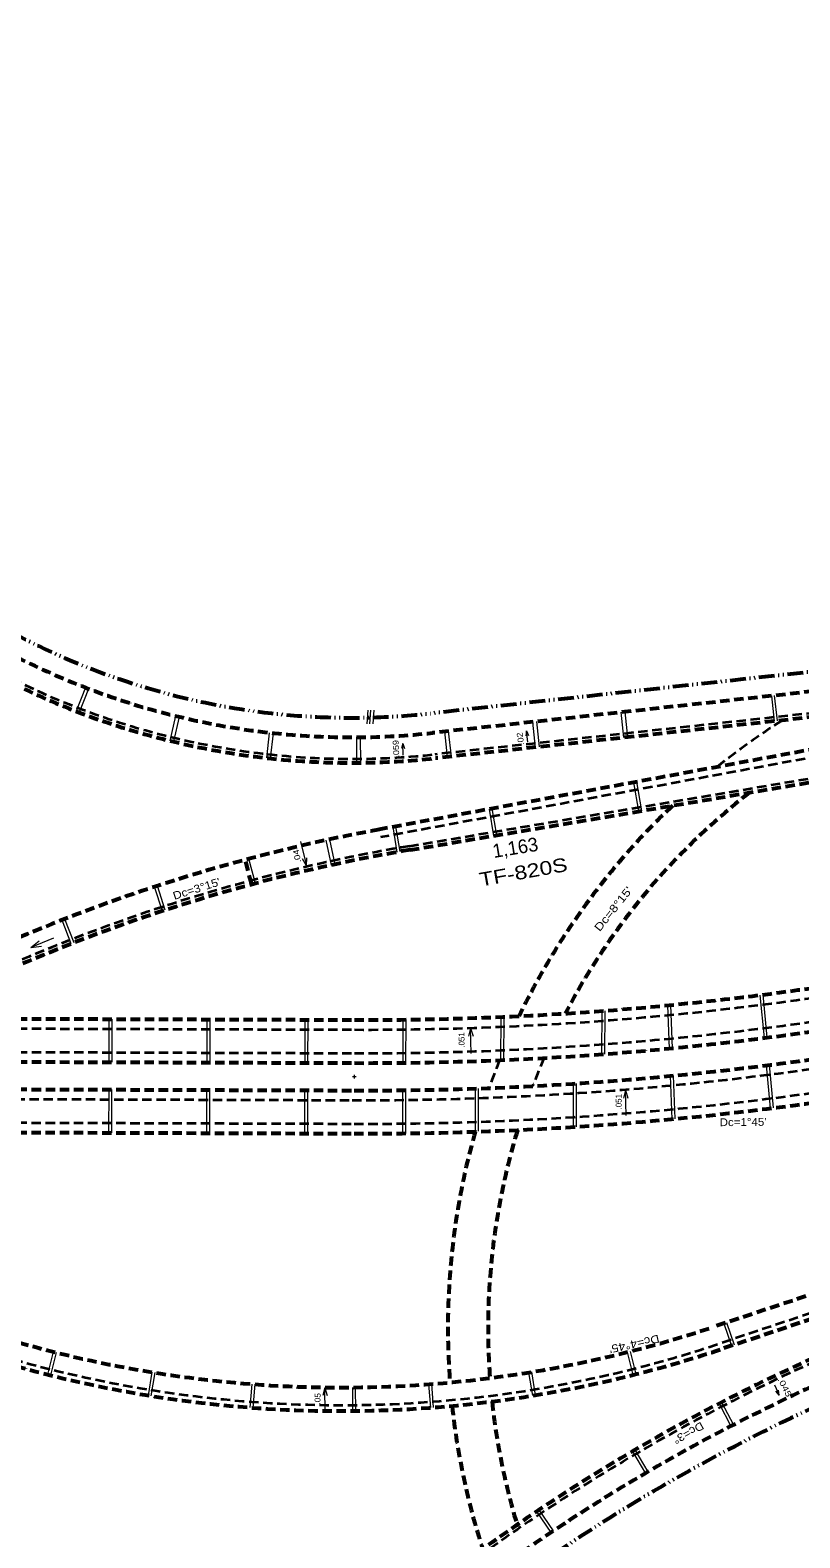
# Model space of a CAD drawing. Extents: x 2354993 to 2372084, y 6966390 to 6990057.
# Drawn here: x 2365274 to 2366060, y 6977519 to 6979057 of the extents above; entities that cross this region are included whole.
import ezdxf

# ---------------------------------------------------------------- set-up
doc = ezdxf.new("R2010")
doc.units = 0
doc.header["$LTSCALE"] = 3.2
doc.linetypes.add('DASH_DOUBLE_DOT', pattern=[9.2, 5, -1.2, 0.3, -1.2, 0.3, -1.2])
doc.linetypes.add('MEDIUM_DASHED', pattern=[4.5, 3, -1.5])
for name, color, linetype, lineweight in [('1', 7, 'Continuous', 13), ('12', 7, 'Continuous', 13), ('13', 7, 'Continuous', 13), ('14', 7, 'Continuous', 13), ('17', 7, 'Continuous', 13), ('19', 7, 'Continuous', 13), ('5', 7, 'Continuous', 35), ('60', 7, 'DASH_DOUBLE_DOT', 53), ('61', 7, 'Continuous', 13), ('7', 7, 'Continuous', 13), ('9', 7, 'Continuous', 13)]:
    doc.layers.add(name, color=color, linetype=linetype, lineweight=lineweight)

msp = doc.modelspace()

# ---------------------------------------------------------------- linework, layer by layer
at = {"layer": '1'}
for p, q in [((2365606.713, 6977989.566), (2365603.213, 6977989.566)), ((2365604.963, 6977991.316), (2365604.963, 6977987.816))]:
    msp.add_line(p, q, dxfattribs=at)
at = {"layer": '12'}
for p, q in [((2366036.779, 6978352.585), (2366033.959, 6978378.408)), ((2366033.797, 6978352.259), (2366030.977, 6978378.083)), ((2365895.358, 6978260.35), (2365890.38, 6978289.832)), ((2365898.314, 6978260.849), (2365893.33, 6978290.377)), ((2365747.452, 6978235.376), (2365742.862, 6978262.562)), ((2365750.406, 6978235.884), (2365745.811, 6978263.107)), ((2365648.848, 6978218.727), (2365644.516, 6978244.382)), ((2365651.801, 6978219.241), (2365647.465, 6978244.927)), ((2365504.061, 6978186.716), (2365497.424, 6978211.855)), ((2365409.176, 6978158.59), (2365401.125, 6978183.312)), ((2365412.028, 6978159.52), (2365403.977, 6978184.244)), ((2365316.038, 6978125.129), (2365306.599, 6978149.356)), ((2365318.832, 6978126.22), (2365309.393, 6978150.447)), ((2366019.03, 6978072.9), (2366023.149, 6978029.071)), ((2366022.008, 6978073.278), (2366026.127, 6978029.447)), ((2365857.509, 6978056.627), (2365857.359, 6978012.494)), ((2365860.51, 6978056.855), (2365860.36, 6978012.718)), ((2365924.585, 6978062.386), (2365926.463, 6978018.363)), ((2365927.576, 6978062.675), (2365929.455, 6978018.651)), ((2365354.478, 6978048.411), (2365354.33, 6978004.411)), ((2365357.477, 6978048.401), (2365357.329, 6978004.4)), ((2365454.478, 6978048.073), (2365454.33, 6978004.072)), ((2365457.477, 6978048.062), (2365457.329, 6978004.062)), ((2365554.478, 6978047.735), (2365554.329, 6978003.735)), ((2365557.477, 6978047.725), (2365557.329, 6978003.724)), ((2365654.478, 6978047.778), (2365654.33, 6978003.772)), ((2365657.478, 6978047.814), (2365657.328, 6978003.809)), ((2365754.488, 6978050.531), (2365754.339, 6978006.484)), ((2365757.488, 6978050.661), (2365757.339, 6978006.613)), ((2366029.859, 6977957.348), (2366025.825, 6978001.187)), ((2366032.838, 6977957.722), (2366028.804, 6978001.563)), ((2365828.595, 6977938.336), (2365828.744, 6977982.437)), ((2365831.596, 6977938.529), (2365831.745, 6977982.633)), ((2365929.451, 6977946.323), (2365927.714, 6977990.356)), ((2365932.442, 6977946.607), (2365930.706, 6977990.642)), ((2365354.235, 6977976.412), (2365354.087, 6977932.413)), ((2365357.234, 6977976.402), (2365357.086, 6977932.403)), ((2365454.235, 6977976.075), (2365454.086, 6977932.076)), ((2365457.234, 6977976.065), (2365457.086, 6977932.065)), ((2365554.235, 6977975.738), (2365554.086, 6977931.738)), ((2365557.234, 6977975.727), (2365557.086, 6977931.728)), ((2365654.235, 6977975.77), (2365654.087, 6977931.765)), ((2365657.235, 6977975.806), (2365657.086, 6977931.8)), ((2365728.579, 6977933.45), (2365728.727, 6977977.48)), ((2365731.581, 6977934.17), (2365731.728, 6977977.585)), ((2365982.067, 6977737.733), (2365989.826, 6977715.021)), ((2365984.913, 6977738.682), (2365992.673, 6977715.97)), ((2365297.64, 6977708.993), (2365291.783, 6977685.719)), ((2365300.55, 6977708.264), (2365294.693, 6977684.989)), ((2365883.51, 6977708.571), (2365889.375, 6977685.299)), ((2365886.419, 6977709.303), (2365892.284, 6977686.031)), ((2365398.24, 6977688.169), (2365394.396, 6977664.478)), ((2365401.201, 6977687.69), (2365397.357, 6977664)), ((2365782.833, 6977687.884), (2365786.685, 6977664.195)), ((2365785.794, 6977688.365), (2365789.646, 6977664.676)), ((2365500.263, 6977676.008), (2365498.461, 6977652.076)), ((2365503.255, 6977675.784), (2365501.453, 6977651.852)), ((2365602.982, 6977672.603), (2365603.236, 6977648.604)), ((2365605.981, 6977672.636), (2365606.236, 6977648.637)), ((2365680.749, 6977675.871), (2365682.559, 6977651.939)), ((2365683.74, 6977676.098), (2365685.55, 6977652.166)), ((2365977.241, 6977656.099), (2365989.317, 6977633.074)), ((2365979.904, 6977657.477), (2365991.981, 6977634.451)), ((2365888.831, 6977607.294), (2365902.095, 6977584.932)), ((2365891.419, 6977608.81), (2365904.683, 6977586.448)), ((2365805.828, 6977524.522), (2365791.253, 6977546.053)), ((2365808.321, 6977526.19), (2365793.746, 6977547.72))]:
    msp.add_line(p, q, dxfattribs=at)
at = {"layer": '14'}
for p, q in [((2365297.86, 6978130.914), (2365274.708, 6978121.481)), ((2365274.708, 6978121.481), (2365283.433, 6978128.312)), ((2365274.708, 6978121.481), (2365285.722, 6978122.692))]:
    msp.add_line(p, q, dxfattribs=at)
at = {"layer": '17'}
for p, q in [((2365786.839, 6978351.434), (2365789.662, 6978325.587)), ((2365790.815, 6978351.868), (2365793.638, 6978326.022)), ((2365880.176, 6978335.474), (2365877.353, 6978361.32)), ((2365884.152, 6978335.908), (2365881.329, 6978361.754)), ((2365515.548, 6978314.718), (2365518.45, 6978340.555)), ((2365519.523, 6978314.271), (2365522.425, 6978340.109)), ((2365607.031, 6978335.843), (2365607.176, 6978309.843)), ((2365611.031, 6978335.865), (2365611.176, 6978309.866)), ((2365696.916, 6978341.612), (2365699.739, 6978315.766)), ((2365700.893, 6978342.047), (2365703.716, 6978316.2)), ((2365575.802, 6978230.807), (2365581.214, 6978205.38)), ((2365579.714, 6978231.639), (2365585.126, 6978206.213))]:
    msp.add_line(p, q, dxfattribs=at)
at = {"layer": '19'}
for p, q in [((2365780.645, 6978342.356), (2365782.732, 6978337.599)), ((2365654.58, 6978329.402), (2365656.047, 6978324.419)), ((2365556.213, 6978204.655), (2365552.077, 6978211.866)), ((2365723.664, 6978038.98), (2365726.134, 6978031.044)), ((2365881.823, 6977975.719), (2365884.293, 6977967.783)), ((2365574.747, 6977672.32), (2365577.217, 6977664.384)), ((2366038.723, 6977664.739), (2366035.349, 6977668.687))]:
    msp.add_line(p, q, dxfattribs=at)
for points in [[(2365782.237, 6978330.745), (2365780.645, 6978342.356), (2365779.914, 6978337.214)], [(2365654.688, 6978317.683), (2365654.58, 6978329.402), (2365653.203, 6978324.394)], [(2365550.003, 6978229.681), (2365556.213, 6978204.655), (2365556.498, 6978212.957)], [(2365724.288, 6978013.204), (2365723.664, 6978038.98), (2365721.582, 6978030.938)], [(2365882.447, 6977949.943), (2365881.823, 6977975.719), (2365879.741, 6977967.677)], [(2365575.371, 6977646.544), (2365574.747, 6977672.32), (2365572.665, 6977664.278)], [(2366033.84, 6977675.392), (2366038.723, 6977664.739), (2366037.935, 6977669.872)]]:
    msp.add_lwpolyline(points, dxfattribs=at)
at = {"layer": '5', "linetype": 'MEDIUM_DASHED'}
for p, q in [((2365661.153, 6978224.869), (2367464.653, 6978529.332)), ((2366433.98, 6978399.985), (2365687.294, 6978318.43)), ((2366277.524, 6978353.263), (2365631.747, 6978233.885)), ((2365246.661, 6977942.775), (2365604.811, 6977941.567)), ((2366276.394, 6977816.868), (2365977.285, 6977717.165))]:
    msp.add_line(p, q, dxfattribs=at)
at = {"layer": '5', "linetype": 'MEDIUM_DASHED', "lineweight": 53}
for p, q in [((2365661.819, 6978220.924), (2366837.203, 6978419.351)), ((2366431.591, 6978421.855), (2365684.905, 6978340.3)), ((2366434.414, 6978396.008), (2365687.728, 6978314.454)), ((2366276.192, 6978361.153), (2365630.415, 6978241.775)), ((2365500.194, 6978185.695), (2365493.557, 6978210.834)), ((2365247.019, 6978048.774), (2365605.169, 6978047.567)), ((2365246.87, 6978004.774), (2365605.02, 6978003.566)), ((2365246.776, 6977976.776), (2365604.926, 6977975.568)), ((2365246.627, 6977932.775), (2365604.777, 6977931.568)), ((2366270.702, 6977833.945), (2365971.593, 6977734.242)), ((2366278.291, 6977811.176), (2365979.182, 6977711.473))]:
    msp.add_line(p, q, dxfattribs=at)
at = {"layer": '5', "linetype": 'MEDIUM_DASHED'}
for points in [[(2365246.984, 6978038.773), (2365605.134, 6978037.566), (2365605.134, 6978037.566)], [(2365246.903, 6978014.774), (2365605.053, 6978013.566), (2365605.053, 6978013.566)], [(2365244.474, 6977966.825), (2365602.624, 6977965.617), (2365602.624, 6977965.616)]]:
    msp.add_lwpolyline(points, dxfattribs=at)
for centre, radius, start, end in [((2365602.828, 6979091.775), 777.944, 184.10654, 276.23324), ((2366434.455, 6977733.014), 733.994, 122.34517, 128.74417), ((2365952.338, 6976500.332), 1748.947, 99.58224, 117.67913), ((2365616.008, 6981263.592), 3226.044, 269.80688, 289.59109), ((2365616.007, 6981263.592), 3250.044, 269.80688, 289.59109), ((2365613.74, 6981263.642), 3298.044, 269.80688, 289.59109), ((2365616.008, 6981263.592), 3322.044, 269.80688, 289.59109), ((2366434.455, 6977733.014), 733.994, 158.12904, 160.50354), ((2366434.455, 6977733.014), 692.994, 156.56104, 159.12091), ((2365591.415, 6978874.774), 1220.227, 230.42494, 288.43495), ((2366864.416, 6975944.503), 1923.859, 114.19652, 168.16581)]:
    msp.add_arc(centre, radius, start, end, dxfattribs=at)
at = {"layer": '5', "linetype": 'MEDIUM_DASHED', "lineweight": 53}
for centre, radius, start, end in [((2365602.828, 6979091.775), 755.944, 184.10697, 276.23324), ((2365602.828, 6979091.775), 781.944, 185.55228, 276.23324), ((2366434.455, 6977733.014), 692.994, 127.95994, 152.40302), ((2366434.455, 6977733.014), 733.994, 133.41282, 154.29392), ((2365952.337, 6976500.333), 1770.947, 100.46125, 118.99651), ((2365952.338, 6976500.332), 1744.947, 99.58224, 117.42976), ((2365616.008, 6981263.592), 3216.044, 269.80688, 280.59288), ((2365616.008, 6981263.592), 3260.044, 269.80688, 280.60229), ((2365616.008, 6981263.592), 3288.044, 269.80688, 280.60814), ((2365616.008, 6981263.592), 3332.044, 269.80688, 280.61714), ((2365591.415, 6978874.774), 1226.227, 230.08464, 288.43495), ((2365591.415, 6978874.774), 1202.227, 231.48183, 288.43495), ((2366434.455, 6977733.014), 733.994, 164.15326, 184.3223), ((2366434.455, 6977733.014), 692.994, 163.03831, 184.20634), ((2366864.416, 6975944.503), 1927.859, 114.19653, 168.16581), ((2366864.416, 6975944.503), 1901.859, 114.19652, 168.16581), ((2366434.455, 6977733.014), 692.994, 186.19198, 197.0075), ((2366434.455, 6977733.014), 733.994, 186.19583, 197.93267)]:
    msp.add_arc(centre, radius, start, end, dxfattribs=at)
at = {"layer": '60'}
msp.add_line((2366092.327, 6978404.919), (2365682.734, 6978360.182), dxfattribs=at)
for centre, radius, start, end in [((2365602.828, 6979091.775), 735.944, 200.58365, 276.23324), ((2366864.416, 6975944.503), 1881.859, 114.65077, 155.69784)]:
    msp.add_arc(centre, radius, start, end, dxfattribs=at)
at = {"layer": '61'}
for p, q in [((2365330.465, 6978386.602), (2365321.097, 6978362.348)), ((2365333.516, 6978385.431), (2365324.253, 6978361.137)), ((2365618.833, 6978363.666), (2365617.747, 6978349.708)), ((2365621.593, 6978363.66), (2365620.508, 6978349.702)), ((2365624.81, 6978363.657), (2365623.724, 6978349.699)), ((2365422.442, 6978357.625), (2365416.505, 6978332.312)), ((2365426.336, 6978356.712), (2365420.4, 6978331.399))]:
    msp.add_line(p, q, dxfattribs=at)
at = {"layer": '9'}
msp.add_arc((2360722.521, 6984327.136), 5729.573, 359.50797, 359.50797, dxfattribs=at)

# ---------------------------------------------------------------- texts
at = {"layer": '12', "width": 1.15}
msp.add_text("Dc=3°15'", height=8, rotation=17.579, dxfattribs=at).set_placement((2365421.284, 6978169.951))
at = {"layer": '13'}
msp.add_text('1,163', height=14, rotation=9.308, dxfattribs=at).set_placement((2365747.262, 6978212.648))
at = {"layer": '13', "width": 1.25}
msp.add_text('TF-820S', height=14, rotation=10.129, dxfattribs=at).set_placement((2365733.855, 6978183.518))
at = {"layer": '19'}
for s, height, rotation, width, p in [('.059', 6, 92.696, 1.15, (2365650.911, 6978315.242)), ('.02', 5.999, 98.143, 1.15, (2365778.312, 6978328.466)), ('.04', 5.999, 101.229, 1.2, (2365550.659, 6978208.678)), ("Dc=8°15'", 8, 51.301, 1.25, (2365855.446, 6978137.024)), ('.045', 6, 296.998, 1.35, (2366036.936, 6977680.82)), ('.05', 6, 88.63, 1.05, (2365570.315, 6977655.035))]:
    msp.add_text(s, height=height, rotation=rotation, dxfattribs=dict(at, width=width)).set_placement(p)
for p in [(2365717.496, 6978019.219), (2365877.839, 6977956.255)]:
    msp.add_text('.051', height=6, rotation=90.548, dxfattribs=at).set_placement(p)
at = {"layer": '7'}
for s, rotation, width, p in [("Dc=1°45'", 0.548, 1.1, (2365977.878, 6977939.086)), ("Dc=4°45'", 192.489, 1.2, (2365915.345, 6977726.476)), ('Dc=3°', 208.969, 1.15, (2365958.866, 6977637.824))]:
    msp.add_text(s, height=8, rotation=rotation, dxfattribs=dict(at, width=width)).set_placement(p)

doc.saveas('drawing.dxf')
